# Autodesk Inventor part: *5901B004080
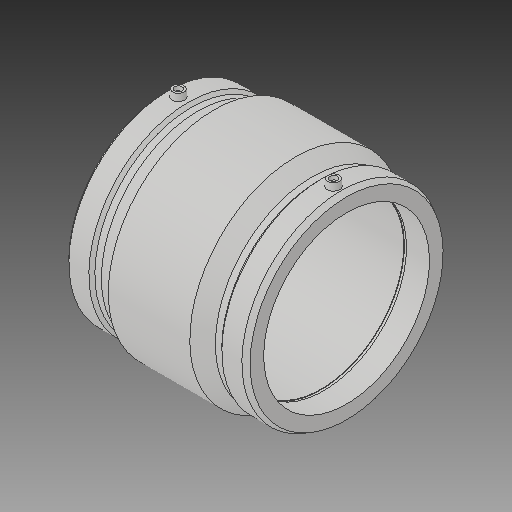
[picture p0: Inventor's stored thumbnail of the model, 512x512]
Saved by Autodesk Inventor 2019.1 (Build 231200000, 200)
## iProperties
Created: 2017-06
Part Number: *5901B004080
Material: Generic
Description: PLASSON IPS COUPLER 8''
Document SubType Name: Modeling
Designer: KIM
Mass: 8622.19 g
Surface Area: 6772.47 cm^2
Volume: 8622.19 cm^3
Density: 1 g/cm^3
Appearance: Default
Author: KIM
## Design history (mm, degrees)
derived "5901B.ipt"
feature "Solid1::5901B.ipt"
tag "TaggingFeature1"
body "Solid1"
other parameters: "d0" = 239.014, "d1" = 218.7, "d2" = 279.4, "d3" = 118.11, "d4" = 59.7535, "d5" = 251.46, "d6" = 174.96, "d7" = 218.7, "d8" = 168 deg, "d10" = 47.244, "d11" = 15.748, "d13" = 239.014, "d14" = 17.6296, "d18" = 218.7, "d19" = 3.52592, "d20" = 168 deg, "d22" = 262.636, "d23" = 279.4, "d24" = 254.75692, "d25" = 135 deg, "d26" = 107.5563, "d27" = 135 deg, "d29" = 139.954, "d30" = 15, "d31" = 83.6549, "d34" = 5 deg, "d35" = 15, "d39" = 5 deg, "d41" = 4, "d42" = 14, "d43" = 0, "d45" = 4, "d46" = 14, "d47" = 0, "d48" = 3, "d49" = 0, "d50" = 3, "d51" = 0, "d52" = 34.2519, "d53" = 8.56297, "d55" = 118.11, "d_" = 218.7, "L_" = 239.014, "L_1" = 118.11, "D_" = 279.4, "A_" = 139.954, "d_2" = 12, "B_" = 139.954
